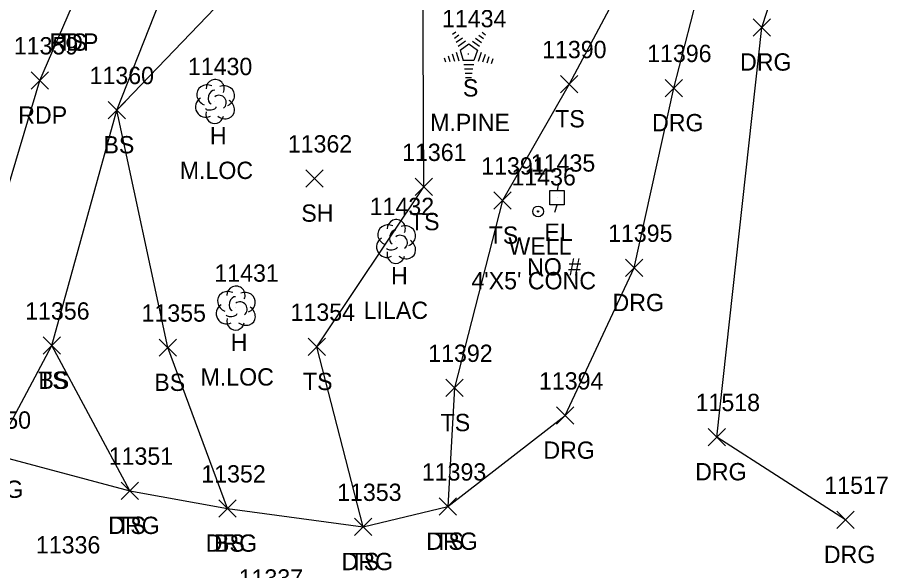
# Model space of a CAD drawing. Extents: x 1475671 to 1477951, y 592661 to 593821.
# Drawn here: x 1476858.4 to 1476958.9, y 593196.5 to 593260.4 of the extents above; entities that cross this region are included whole.
import ezdxf

# ---------------------------------------------------------------- set-up
doc = ezdxf.new("R2010")
doc.units = 0
for name, color, linetype in [('L_A', 7, 'Continuous'), ('L_C', 7, 'Continuous'), ('L_I', 7, 'Continuous'), ('L_TIC', 7, 'Continuous'), ('LELB', 7, 'Continuous'), ('LTC', 7, 'Continuous'), ('LTD', 7, 'Continuous'), ('P_A', 7, 'Continuous'), ('P_I', 7, 'Continuous'), ('P_TIC', 7, 'Continuous'), ('PET', 7, 'Continuous'), ('R_A', 7, 'Continuous'), ('R_I', 7, 'Continuous'), ('R_TIC', 7, 'Continuous'), ('RDG', 7, 'Continuous'), ('U_A', 7, 'Continuous'), ('U_C', 7, 'Continuous'), ('U_I', 7, 'Continuous'), ('UEPT', 7, 'Continuous'), ('UWW', 7, 'Continuous')]:
    doc.layers.add(name, color=color, linetype=linetype)

msp = doc.modelspace()

# ---------------------------------------------------------------- linework, layer by layer
at = {"layer": 'L_TIC'}
for points in [[(1476921.08, 593251.68), (1476923.08, 593253.68)], [(1476923.08, 593251.68), (1476921.08, 593253.68)], [(1476868.87, 593248.68), (1476870.87, 593250.68)], [(1476870.87, 593248.68), (1476868.87, 593250.68)], [(1476868.87, 593248.68), (1476870.87, 593250.68)], [(1476870.87, 593248.68), (1476868.87, 593250.68)], [(1476891.67, 593240.78), (1476893.67, 593242.78)], [(1476893.67, 593240.78), (1476891.67, 593242.78)], [(1476904.3, 593239.8), (1476906.3, 593241.8)], [(1476906.3, 593239.8), (1476904.3, 593241.8)], [(1476913.39, 593238.23), (1476915.39, 593240.23)], [(1476915.39, 593238.23), (1476913.39, 593240.23)], [(1476861.35, 593221.47), (1476863.35, 593223.47)], [(1476863.35, 593221.47), (1476861.35, 593223.47)], [(1476861.35, 593221.47), (1476863.35, 593223.47)], [(1476863.35, 593221.47), (1476861.35, 593223.47)], [(1476874.74, 593221.23), (1476876.74, 593223.23)], [(1476876.74, 593221.23), (1476874.74, 593223.23)], [(1476891.94, 593221.33), (1476893.94, 593223.33)], [(1476893.94, 593221.33), (1476891.94, 593223.33)], [(1476907.84, 593216.58), (1476909.84, 593218.58)], [(1476909.84, 593216.58), (1476907.84, 593218.58)], [(1476870.37, 593204.7), (1476872.37, 593206.7)], [(1476872.37, 593204.7), (1476870.37, 593206.7)], [(1476907.1, 593202.87), (1476909.1, 593204.87)], [(1476909.1, 593202.87), (1476907.1, 593204.87)], [(1476881.63, 593202.65), (1476883.63, 593204.65)], [(1476883.63, 593202.65), (1476881.63, 593204.65)], [(1476897.32, 593200.52), (1476899.32, 593202.52)], [(1476899.32, 593200.52), (1476897.32, 593202.52)]]:
    msp.add_lwpolyline(points, dxfattribs=at)
at = {"layer": 'LELB'}
for points in [[(1476844.89, 593161.77), (1476849.57, 593180.8), (1476849.13, 593190.54), (1476855.62, 593209.87), (1476862.35, 593222.47), (1476869.87, 593249.68), (1476878.56, 593271.73), (1476877.88, 593280.96), (1476889.82, 593301.6), (1476893.1, 593318.84), (1476908.59, 593341.2), (1476918.55, 593355.38), (1476919.84, 593361.76), (1476917.93, 593365.87), (1476921.61, 593367.66), (1476922.08, 593366.69), (1476922.63, 593360.35), (1476925.59, 593366.62)], [(1476882.63, 593203.65), (1476875.74, 593222.23), (1476869.87, 593249.68), (1476888.77, 593269.4), (1476896.32, 593282.96), (1476889.82, 593301.6), (1476899.08, 593309.06), (1476918.96, 593334.82), (1476923.19, 593355.07), (1476922.63, 593360.35)], [(1476913.56, 593289.25), (1476929.5, 593290.79), (1476932.29, 593271.86), (1476922.08, 593252.68), (1476914.39, 593239.23), (1476908.84, 593217.58), (1476908.1, 593203.87)], [(1476898.32, 593201.52), (1476892.94, 593222.33), (1476905.3, 593240.8), (1476905.18, 593266.71), (1476908.62, 593285.82), (1476913.56, 593289.25)], [(1476871.37, 593205.7), (1476862.35, 593222.47)]]:
    msp.add_lwpolyline(points, dxfattribs=at)
at = {"layer": 'LTC'}
for p, q in [((1476908.63, 593258.45), (1476908.99, 593258.71)), ((1476908.84, 593257.99), (1476909.37, 593258.37)), ((1476909.05, 593257.52), (1476909.76, 593258.03)), ((1476911.66, 593258.35), (1476912.21, 593257.95)), ((1476912.03, 593258.69), (1476912.45, 593258.39)), ((1476909.26, 593257.06), (1476910.14, 593257.69)), ((1476909.49, 593256.6), (1476910.5, 593257.34)), ((1476910.5, 593257.34), (1476911.49, 593256.61)), ((1476910.92, 593257.65), (1476911.73, 593257.06)), ((1476911.29, 593258), (1476911.97, 593257.5)), ((1476908.58, 593256.17), (1476908.85, 593255.33)), ((1476909.03, 593256.38), (1476909.36, 593255.36)), ((1476909.49, 593256.6), (1476909.87, 593255.41)), ((1476911.49, 593256.61), (1476911.1, 593255.41)), ((1476911.93, 593256.34), (1476911.59, 593255.3)), ((1476912.38, 593256.09), (1476912.09, 593255.21)), ((1476907.67, 593255.73), (1476907.82, 593255.27)), ((1476908.12, 593255.95), (1476908.33, 593255.3)), ((1476911.1, 593255.41), (1476909.87, 593255.41)), ((1476912.82, 593255.84), (1476912.58, 593255.11)), ((1476913.27, 593255.59), (1476913.08, 593255.02)), ((1476911.07, 593254.91), (1476909.92, 593254.91)), ((1476910.98, 593254.41), (1476909.99, 593254.41)), ((1476910.9, 593253.91), (1476910.07, 593253.91)), ((1476910.81, 593253.41), (1476910.14, 593253.41))]:
    msp.add_line(p, q, dxfattribs=at)
at = {"layer": 'LTD'}
for p, q in [((1476881.17, 593250.72), (1476881.17, 593250.72)), ((1476881.17, 593250.72), (1476881.17, 593250.72)), ((1476902.09, 593234.55), (1476902.09, 593234.55)), ((1476902.09, 593234.55), (1476902.09, 593234.55)), ((1476883.58, 593226.85), (1476883.58, 593226.85)), ((1476883.58, 593226.85), (1476883.58, 593226.85))]:
    msp.add_line(p, q, dxfattribs=at)
for centre in [(1476881.22, 593252.16), (1476902.13, 593235.98), (1476883.62, 593228.29)]:
    msp.add_arc(centre, 1.05, 335.5272, 180.9563, dxfattribs=at)
for centre, major_axis, ratio, start_param, end_param in [((1476880.38, 593251.39), (1.21, -0.51), 0.895232, 1.570796, 4.712389), ((1476880.96, 593251.18), (-0.208, -0.792), 0.645439, 3.141593, 6.283185), ((1476882.21, 593251.31), (-1.14, -0.48), 0.949671, 1.570796, 4.712389), ((1476880.09, 593250.02), (0.58, -1.04), 0.959034, 3.141593, 6.283185), ((1476881.67, 593250.56), (-0.5, 0.667), 0.989748, 3.141593, 6.283185), ((1476880.71, 593249.97), (-0.625, -0.083), 0.423636, 0, 3.141593), ((1476882.17, 593249.89), (-1.09, 0.79), 0.841452, 1.570796, 4.712389), ((1476881.17, 593249.22), (0.26, 1.06), 0.942809, 1.570796, 4.712389), ((1476901.29, 593235.22), (1.21, -0.51), 0.895232, 1.570796, 4.712389), ((1476903.13, 593235.13), (-1.14, -0.48), 0.949671, 1.570796, 4.712389), ((1476901.88, 593235.01), (-0.208, -0.792), 0.645439, 3.141593, 6.283185), ((1476902.59, 593234.38), (-0.5, 0.667), 0.989748, 3.141593, 6.283185), ((1476901, 593233.84), (0.58, -1.04), 0.959034, 3.141593, 6.283185), ((1476903.09, 593233.72), (-1.09, 0.79), 0.841452, 1.570796, 4.712389), ((1476902.09, 593233.05), (0.26, 1.06), 0.942809, 1.570796, 4.712389), ((1476901.63, 593233.8), (-0.625, -0.083), 0.423636, 0, 3.141593), ((1476882.78, 593227.52), (1.21, -0.51), 0.895232, 1.570796, 4.712389), ((1476883.37, 593227.31), (-0.208, -0.792), 0.645439, 3.141593, 6.283185), ((1476884.62, 593227.44), (-1.14, -0.48), 0.949671, 1.570796, 4.712389), ((1476882.49, 593226.14), (0.58, -1.04), 0.959034, 3.141593, 6.283185), ((1476884.08, 593226.69), (-0.5, 0.667), 0.989748, 3.141593, 6.283185), ((1476884.58, 593226.02), (-1.09, 0.79), 0.841452, 1.570796, 4.712389), ((1476883.12, 593226.1), (-0.625, -0.083), 0.423636, 0, 3.141593), ((1476883.58, 593225.35), (0.26, 1.06), 0.942809, 1.570796, 4.712389)]:
    msp.add_ellipse(centre, major_axis=major_axis, ratio=ratio, start_param=start_param, end_param=end_param, dxfattribs=at)
at = {"layer": 'P_TIC'}
for points in [[(1476859.98, 593252.11), (1476861.98, 593254.11)], [(1476861.98, 593252.11), (1476859.98, 593254.11)]]:
    msp.add_lwpolyline(points, dxfattribs=at)
at = {"layer": 'PET'}
msp.add_lwpolyline([(1476852.05, 593085.53), (1476845.73, 593108.15), (1476841.01, 593134.78), (1476840.06, 593162.08), (1476843.4, 593187.72), (1476850.39, 593217.62), (1476860.98, 593253.11), (1476864.6, 593261.54), (1476871.79, 593281.35), (1476880.28, 593307.27), (1476885.63, 593321.18), (1476897.83, 593348.03), (1476918.01, 593376.95)], dxfattribs=at)
at = {"layer": 'R_TIC'}
for points in [[(1476943.34, 593258.24), (1476945.34, 593260.24)], [(1476945.34, 593258.24), (1476943.34, 593260.24)], [(1476933.18, 593251.23), (1476935.18, 593253.23)], [(1476935.18, 593251.23), (1476933.18, 593253.23)], [(1476928.61, 593230.45), (1476930.61, 593232.45)], [(1476930.61, 593230.45), (1476928.61, 593232.45)], [(1476920.63, 593213.39), (1476922.63, 593215.39)], [(1476922.63, 593213.39), (1476920.63, 593215.39)], [(1476938.16, 593210.9), (1476940.16, 593212.9)], [(1476940.16, 593210.9), (1476938.16, 593212.9)], [(1476870.37, 593204.7), (1476872.37, 593206.7)], [(1476872.37, 593204.7), (1476870.37, 593206.7)], [(1476907.1, 593202.87), (1476909.1, 593204.87)], [(1476909.1, 593202.87), (1476907.1, 593204.87)], [(1476881.63, 593202.65), (1476883.63, 593204.65)], [(1476883.63, 593202.65), (1476881.63, 593204.65)], [(1476953.02, 593201.34), (1476955.02, 593203.34)], [(1476955.02, 593201.34), (1476953.02, 593203.34)], [(1476897.32, 593200.52), (1476899.32, 593202.52)], [(1476899.32, 593200.52), (1476897.32, 593202.52)]]:
    msp.add_lwpolyline(points, dxfattribs=at)
at = {"layer": 'RDG'}
for points in [[(1476954.02, 593202.34), (1476939.16, 593211.9), (1476944.34, 593259.24), (1476951.52, 593281.23), (1476953.96, 593319.9), (1476951.87, 593341.86), (1476947.54, 593363.24), (1476941.61, 593379.55), (1476939.44, 593381.51), (1476939.12, 593387.06), (1476944.23, 593398.87)], [(1476850.39, 593217.62), (1476855.62, 593209.87), (1476871.37, 593205.7), (1476882.63, 593203.65), (1476898.32, 593201.52), (1476908.1, 593203.87), (1476921.63, 593214.39), (1476929.61, 593231.45), (1476934.18, 593252.23), (1476938.78, 593270.03), (1476944.38, 593296.1), (1476944.94, 593325.58), (1476942.87, 593338.88), (1476933.5, 593367.74), (1476927.3, 593373.86), (1476918.01, 593376.95)]]:
    msp.add_lwpolyline(points, dxfattribs=at)
at = {"layer": 'UEPT'}
for p, q in [((1476920.86, 593241.23), (1476920.69, 593240.4)), ((1476919.86, 593238.73), (1476919.86, 593240.4)), ((1476919.86, 593240.4), (1476921.53, 593240.4)), ((1476921.53, 593240.4), (1476921.53, 593238.73)), ((1476920.69, 593239.57), (1476920.69, 593239.57)), ((1476921.53, 593238.73), (1476919.86, 593238.73)), ((1476920.44, 593237.9), (1476920.69, 593238.73))]:
    msp.add_line(p, q, dxfattribs=at)
at = {"layer": 'UWW'}
for radius in [0.625, 0.0833]:
    msp.add_circle((1476918.51, 593237.97), radius, dxfattribs=at)

# ---------------------------------------------------------------- texts
at = {"layer": 'L_A'}
for s, p in [('TS', (1476863.01, 593256.54)), ('S', (1476909.82, 593251.25)), ('TS', (1476920.48, 593247.68)), ('H', (1476880.6, 593245.72)), ('BS', (1476868.31, 593244.68)), ('BS', (1476868.31, 593244.68)), ('SH', (1476891.16, 593236.78)), ('TS', (1476903.71, 593235.8)), ('TS', (1476912.8, 593234.23)), ('H', (1476901.52, 593229.55)), ('H', (1476883.01, 593221.85)), ('TS', (1476860.76, 593217.47)), ('BS', (1476860.79, 593217.47)), ('BS', (1476874.18, 593217.23)), ('TS', (1476891.35, 593217.33)), ('TS', (1476907.25, 593212.58)), ('TS', (1476869.78, 593200.7)), ('TS', (1476906.51, 593198.87)), ('BS', (1476881.07, 593198.65)), ('TS', (1476896.73, 593196.52))]:
    msp.add_text(s, height=2, dxfattribs=at).set_placement(p)
at = {"layer": 'L_C'}
for s, p in [('M.PINE', (1476906.04, 593247.25)), ('M.LOC', (1476877.12, 593241.72)), ('LILAC', (1476898.36, 593225.55)), ('M.LOC', (1476879.52, 593217.85))]:
    msp.add_text(s, height=2, dxfattribs=at).set_placement(p)
at = {"layer": 'L_I'}
for s, p in [('11434', (1476907.41, 593259.25)), ('11390', (1476918.97, 593255.68)), ('11430', (1476878.06, 593253.72)), ('11360', (1476866.71, 593252.68)), ('11360', (1476866.71, 593252.68)), ('11362', (1476889.6, 593244.78)), ('11361', (1476902.8, 593243.8)), ('11391', (1476911.94, 593242.23)), ('11432', (1476899.06, 593237.55)), ('11431', (1476881.12, 593229.85)), ('11356', (1476859.27, 593225.47)), ('11356', (1476859.27, 593225.47)), ('11355', (1476872.71, 593225.23)), ('11354', (1476889.92, 593225.33)), ('11392', (1476905.82, 593220.58)), ('11350', (1476852.51, 593212.87)), ('11351', (1476868.92, 593208.7)), ('11393', (1476905.08, 593206.87)), ('11352', (1476879.61, 593206.65)), ('11353', (1476895.3, 593204.52))]:
    msp.add_text(s, height=2, dxfattribs=at).set_placement(p)
at = {"layer": 'LTC'}
msp.add_text('.', height=1.04, rotation=270, dxfattribs=at).set_placement((1476910.38, 593256.35))
at = {"layer": 'P_A'}
for p in [(1476862.08, 593256.54), (1476858.47, 593248.11)]:
    msp.add_text('RDP', height=2, dxfattribs=at).set_placement(p)
at = {"layer": 'P_I'}
msp.add_text('11359', height=2, dxfattribs=at).set_placement((1476857.95, 593256.11))
at = {"layer": 'R_A'}
for p in [(1476941.83, 593254.24), (1476931.67, 593247.23), (1476927.1, 593226.45), (1476919.12, 593209.39), (1476936.64, 593206.9), (1476853.11, 593204.87), (1476868.86, 593200.7), (1476905.59, 593198.87), (1476880.12, 593198.65), (1476951.51, 593197.34), (1476895.81, 593196.52)]:
    msp.add_text('DRG', height=2, dxfattribs=at).set_placement(p)
at = {"layer": 'R_I'}
for s, p in [('11396', (1476931.1, 593255.23)), ('11395', (1476926.59, 593234.45)), ('11394', (1476918.61, 593217.39)), ('11518', (1476936.7, 593214.9)), ('11350', (1476852.51, 593212.87)), ('11351', (1476868.92, 593208.7)), ('11393', (1476905.08, 593206.87)), ('11352', (1476879.61, 593206.65)), ('11517', (1476951.57, 593205.34)), ('11353', (1476895.3, 593204.52)), ('11336', (1476860.51, 593198.45)), ('11337', (1476883.93, 593194.62))]:
    msp.add_text(s, height=2, dxfattribs=at).set_placement(p)
at = {"layer": 'U_A'}
for s, p in [('EL', (1476919.23, 593234.57)), ('WELL', (1476915.08, 593232.97))]:
    msp.add_text(s, height=2, dxfattribs=at).set_placement(p)
at = {"layer": 'U_C'}
for s, p in [('NO #', (1476917.23, 593230.57)), ("4'X5' CONC", (1476910.8, 593228.97))]:
    msp.add_text(s, height=2, dxfattribs=at).set_placement(p)
at = {"layer": 'U_I'}
for s, p in [('11435', (1476917.67, 593242.57)), ('11436', (1476915.43, 593240.97))]:
    msp.add_text(s, height=2, dxfattribs=at).set_placement(p)

doc.saveas('drawing.dxf')
